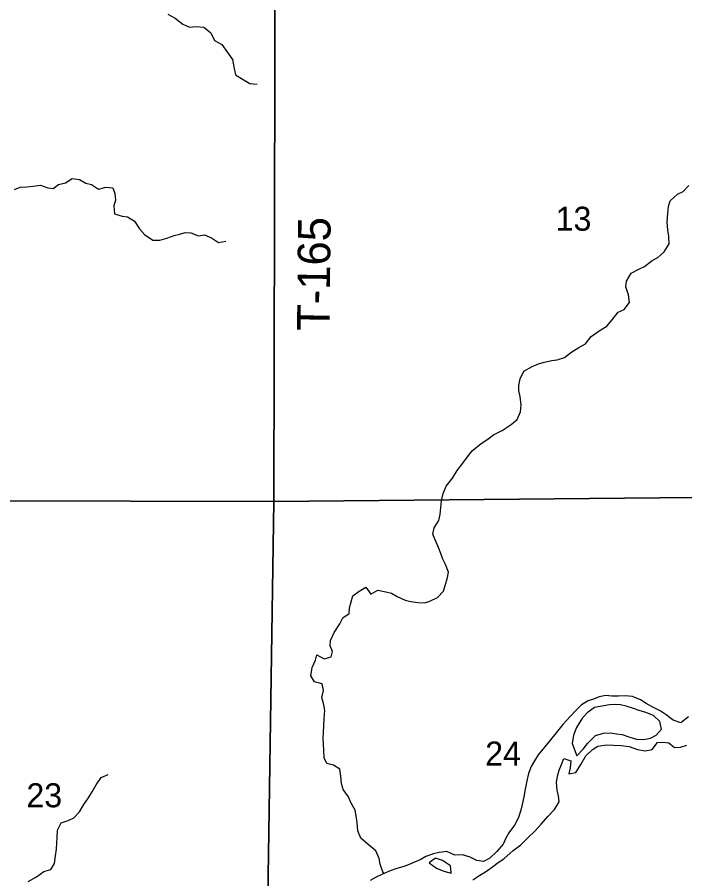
# Model space of a CAD drawing. Extents: x 1772825 to 1773716, y 1138558 to 1139032.
# Drawn here: x 1772830.255 to 1772830.837, y 1138559.298 to 1138560.049 of the extents above; entities that cross this region are included whole.
import ezdxf

# ---------------------------------------------------------------- set-up
doc = ezdxf.new("R2010")
doc.units = 0
for name, color, linetype in [('GM_X_Major_River', 7, 'Continuous'), ('GM_X_Minor_River', 7, 'Continuous'), ('GM_X_Section', 7, 'Continuous'), ('GM_X_Section_Text', 7, 'Continuous'), ('GM_X_Township_Road_Text', 7, 'Continuous')]:
    doc.layers.add(name, color=color, linetype=linetype)

msp = doc.modelspace()

# ---------------------------------------------------------------- linework, layer by layer
at = {"layer": 'GM_X_Major_River'}
for points in [[(1772830.84014, 1138559.43888), (1772830.83347, 1138559.43379), (1772830.82684, 1138559.43591), (1772830.8206, 1138559.44068), (1772830.81549, 1138559.44412), (1772830.80905, 1138559.44718), (1772830.80337, 1138559.45043), (1772830.79825, 1138559.45368), (1772830.79143, 1138559.45655), (1772830.78498, 1138559.45715), (1772830.7791, 1138559.45699), (1772830.77341, 1138559.45701), (1772830.76809, 1138559.45741), (1772830.76221, 1138559.4563), (1772830.75745, 1138559.45423), (1772830.7527, 1138559.45292), (1772830.74699, 1138559.44934), (1772830.74223, 1138559.44462), (1772830.73689, 1138559.43914), (1772830.7306, 1138559.43214), (1772830.72468, 1138559.42496), (1772830.71991, 1138559.41872), (1772830.71476, 1138559.41229), (1772830.70923, 1138559.40586), (1772830.70579, 1138559.40056), (1772830.70311, 1138559.39545), (1772830.70081, 1138559.38938), (1772830.69926, 1138559.38313), (1772830.69772, 1138559.37573), (1772830.69655, 1138559.3691), (1772830.69519, 1138559.36246), (1772830.69403, 1138559.35734), (1772830.69192, 1138559.35109), (1772830.68847, 1138559.34446), (1772830.68351, 1138559.33784), (1772830.68083, 1138559.33292), (1772830.67853, 1138559.3278), (1772830.67319, 1138559.32137), (1772830.6669, 1138559.31552), (1772830.66158, 1138559.31269), (1772830.6557, 1138559.31367), (1772830.64983, 1138559.31635), (1772830.64319, 1138559.31847), (1772830.63655, 1138559.31811), (1772830.62954, 1138559.32137), (1772830.62289, 1138559.32045), (1772830.61796, 1138559.31952), (1772830.61111, 1138559.31708), (1772830.60636, 1138559.31426), (1772830.60141, 1138559.312), (1772830.59666, 1138559.31012), (1772830.59191, 1138559.30844), (1772830.58507, 1138559.30638), (1772830.58012, 1138559.3045), (1772830.57347, 1138559.30168), (1772830.56738, 1138559.29867), (1772830.56263, 1138559.29604)], [(1772830.81573, 1138559.4321), (1772830.81507, 1138559.43482), (1772830.80978, 1138559.44015), (1772830.80295, 1138559.44265), (1772830.79727, 1138559.44438), (1772830.79234, 1138559.44611), (1772830.78571, 1138559.44823), (1772830.78078, 1138559.44939), (1772830.77603, 1138559.4496), (1772830.77129, 1138559.44924), (1772830.75837, 1138559.44702), (1772830.7519, 1138559.4423), (1772830.74713, 1138559.43701), (1772830.74254, 1138559.42963), (1772830.74005, 1138559.4228), (1772830.73888, 1138559.4156), (1772830.74282, 1138559.40495)], [(1772830.74282, 1138559.40495), (1772830.74835, 1138559.41062), (1772830.75216, 1138559.41554), (1772830.75903, 1138559.42253), (1772830.76606, 1138559.42459), (1772830.77232, 1138559.42494), (1772830.77744, 1138559.42416), (1772830.78237, 1138559.42338), (1772830.78901, 1138559.42127), (1772830.79488, 1138559.41953), (1772830.80134, 1138559.41913), (1772830.80703, 1138559.42024), (1772830.81198, 1138559.42288), (1772830.81675, 1138559.42798), (1772830.81573, 1138559.4321)], [(1772830.65202, 1138559.29679), (1772830.6583, 1138559.30075), (1772830.66306, 1138559.30377), (1772830.66915, 1138559.30811), (1772830.6741, 1138559.31188), (1772830.67924, 1138559.31508), (1772830.68743, 1138559.32226), (1772830.69409, 1138559.32736), (1772830.70019, 1138559.3334), (1772830.70629, 1138559.33907), (1772830.71182, 1138559.34512), (1772830.71754, 1138559.35193), (1772830.72345, 1138559.35816), (1772830.72728, 1138559.36479), (1772830.72673, 1138559.37011), (1772830.7258, 1138559.37504), (1772830.72507, 1138559.3815), (1772830.72604, 1138559.38719), (1772830.72739, 1138559.39231), (1772830.72931, 1138559.39742), (1772830.73142, 1138559.40254), (1772830.73749, 1138559.40061), (1772830.73708, 1138559.39435), (1772830.73573, 1138559.38923), (1772830.74181, 1138559.39035), (1772830.74639, 1138559.39716), (1772830.75079, 1138559.40473), (1772830.75651, 1138559.4104), (1772830.76127, 1138559.41342), (1772830.76886, 1138559.41433), (1772830.77493, 1138559.41431), (1772830.78157, 1138559.4139), (1772830.78859, 1138559.41311), (1772830.79579, 1138559.41042), (1772830.80243, 1138559.40925), (1772830.80851, 1138559.41037), (1772830.81309, 1138559.41661), (1772830.81784, 1138559.41678), (1772830.82296, 1138559.41619), (1772830.82788, 1138559.41218), (1772830.83319, 1138559.41254), (1772830.8387, 1138559.41403)], [(1772830.63282, 1138559.30637), (1772830.63253, 1138559.30902), (1772830.62571, 1138559.31342), (1772830.61965, 1138559.31553), (1772830.61394, 1138559.31157)], [(1772830.61394, 1138559.31157), (1772830.62056, 1138559.3068), (1772830.627, 1138559.3043), (1772830.63326, 1138559.30257), (1772830.63282, 1138559.30637)]]:
    msp.add_lwpolyline(points, dxfattribs=at)
at = {"layer": 'GM_X_Minor_River'}
for points in [[(1772830.3861, 1138560.05166), (1772830.39273, 1138560.04822), (1772830.39916, 1138560.04307), (1772830.40522, 1138560.04057), (1772830.41092, 1138560.04112), (1772830.41756, 1138560.04033), (1772830.4238, 1138560.03537), (1772830.427, 1138560.02872), (1772830.43325, 1138560.02528), (1772830.43815, 1138560.01823), (1772830.44268, 1138560.01214), (1772830.44379, 1138560.00588), (1772830.44509, 1138559.99885), (1772830.4519, 1138559.99484), (1772830.45758, 1138559.9914), (1772830.46403, 1138559.9908)], [(1772830.25259, 1138559.89891), (1772830.25734, 1138559.90098), (1772830.26323, 1138559.90115), (1772830.26892, 1138559.90188), (1772830.27519, 1138559.90261), (1772830.28144, 1138559.90031), (1772830.28619, 1138559.89972), (1772830.29095, 1138559.90331), (1772830.29703, 1138559.9048), (1772830.30293, 1138559.90857), (1772830.30918, 1138559.90759), (1772830.31467, 1138559.90434), (1772830.31961, 1138559.90318), (1772830.32585, 1138559.89917), (1772830.33231, 1138559.90085), (1772830.33819, 1138559.90026), (1772830.33988, 1138559.89551), (1772830.34061, 1138559.88962), (1772830.33907, 1138559.88469), (1772830.3398, 1138559.87767), (1772830.34625, 1138559.87555), (1772830.35118, 1138559.87515), (1772830.35724, 1138559.87114), (1772830.36157, 1138559.86467), (1772830.36592, 1138559.85972), (1772830.37311, 1138559.85476), (1772830.37918, 1138559.85473), (1772830.38526, 1138559.85641), (1772830.39173, 1138559.85885), (1772830.39667, 1138559.85997), (1772830.40142, 1138559.86128), (1772830.40616, 1138559.86107), (1772830.41298, 1138559.85857), (1772830.4183, 1138559.85931), (1772830.42436, 1138559.85663), (1772830.43042, 1138559.85262), (1772830.43669, 1138559.85373)], [(1772830.72568, 1138559.7504), (1772830.73195, 1138559.75227), (1772830.73843, 1138559.75718), (1772830.74452, 1138559.76095), (1772830.75042, 1138559.76434), (1772830.75519, 1138559.77058), (1772830.76242, 1138559.77548), (1772830.76889, 1138559.77963), (1772830.77366, 1138559.7853), (1772830.779, 1138559.79192), (1772830.78395, 1138559.79417), (1772830.78872, 1138559.80042), (1772830.78799, 1138559.80687), (1772830.78555, 1138559.8139), (1772830.78614, 1138559.81902), (1772830.79034, 1138559.82584), (1772830.79681, 1138559.82922), (1772830.80176, 1138559.83167), (1772830.80861, 1138559.83695), (1772830.81356, 1138559.83959), (1772830.81889, 1138559.8445), (1772830.82329, 1138559.8515), (1772830.82294, 1138559.85795), (1772830.8222, 1138559.86327), (1772830.82166, 1138559.87067), (1772830.82208, 1138559.87826), (1772830.82286, 1138559.88395), (1772830.82421, 1138559.88907), (1772830.83069, 1138559.89473), (1772830.83563, 1138559.89718), (1772830.8404, 1138559.90247)], [(1772830.57455, 1138559.30214), (1772830.57367, 1138559.30377), (1772830.57142, 1138559.31023), (1772830.57049, 1138559.31536), (1772830.56748, 1138559.32201), (1772830.56086, 1138559.32755), (1772830.55462, 1138559.33308), (1772830.55199, 1138559.33954), (1772830.55126, 1138559.34675), (1772830.55053, 1138559.35264), (1772830.5496, 1138559.35758), (1772830.54583, 1138559.36405), (1772830.54377, 1138559.36899), (1772830.53905, 1138559.37546), (1772830.53755, 1138559.38059), (1772830.53701, 1138559.38704), (1772830.53609, 1138559.39331), (1772830.53079, 1138559.39675), (1772830.52491, 1138559.3981), (1772830.52265, 1138559.40305), (1772830.52211, 1138559.40969), (1772830.52194, 1138559.41482), (1772830.52159, 1138559.41994), (1772830.5218, 1138559.42525), (1772830.5222, 1138559.43133), (1772830.52242, 1138559.4374), (1772830.52302, 1138559.44442), (1772830.52209, 1138559.44935), (1772830.52041, 1138559.45562), (1772830.52195, 1138559.46188), (1772830.52065, 1138559.46777), (1772830.5142, 1138559.46931), (1772830.511, 1138559.47464), (1772830.51198, 1138559.48204), (1772830.51485, 1138559.48829), (1772830.5162, 1138559.49303), (1772830.52245, 1138559.48939), (1772830.52872, 1138559.49126), (1772830.52969, 1138559.49601), (1772830.52781, 1138559.50076), (1772830.52802, 1138559.5055), (1772830.53127, 1138559.51251), (1772830.53605, 1138559.51989), (1772830.53892, 1138559.52519), (1772830.54444, 1138559.52915), (1772830.54465, 1138559.53408), (1772830.54619, 1138559.5392), (1772830.54754, 1138559.54451), (1772830.55306, 1138559.54847), (1772830.55896, 1138559.55186), (1772830.5633, 1138559.54596), (1772830.5692, 1138559.54935), (1772830.57641, 1138559.5478), (1772830.58115, 1138559.54683), (1772830.58607, 1138559.54378), (1772830.59327, 1138559.54071), (1772830.59801, 1138559.53936), (1772830.60427, 1138559.53857), (1772830.60996, 1138559.53836), (1772830.61471, 1138559.53967), (1772830.62136, 1138559.54287), (1772830.6267, 1138559.54835), (1772830.62805, 1138559.55346), (1772830.62998, 1138559.56029), (1772830.63095, 1138559.56503), (1772830.62832, 1138559.57168), (1772830.62606, 1138559.57644), (1772830.62438, 1138559.58138), (1772830.62212, 1138559.58651), (1772830.6193, 1138559.59316), (1772830.61723, 1138559.59829), (1772830.6184, 1138559.6036), (1772830.6226, 1138559.61004), (1772830.62376, 1138559.61535), (1772830.62435, 1138559.62142), (1772830.62495, 1138559.6273), (1772830.62631, 1138559.63374), (1772830.6288, 1138559.64018), (1772830.63433, 1138559.64699), (1772830.63835, 1138559.65381), (1772830.64254, 1138559.6591), (1772830.64751, 1138559.66553), (1772830.6517, 1138559.67083), (1772830.65951, 1138559.67744), (1772830.66446, 1138559.68064), (1772830.67017, 1138559.68479), (1772830.67759, 1138559.68874), (1772830.68559, 1138559.69383), (1772830.69073, 1138559.69837), (1772830.69379, 1138559.7048), (1772830.69439, 1138559.71087), (1772830.69328, 1138559.71828), (1772830.69235, 1138559.72322), (1772830.69237, 1138559.72796), (1772830.69335, 1138559.73384), (1772830.6966, 1138559.74028), (1772830.70383, 1138559.74442), (1772830.70934, 1138559.74667), (1772830.71448, 1138559.74817), (1772830.72094, 1138559.74966), (1772830.72568, 1138559.7504)], [(1772830.26428, 1138559.29522), (1772830.2717, 1138559.29936), (1772830.27798, 1138559.30389), (1772830.28406, 1138559.30576), (1772830.28731, 1138559.31087), (1772830.28828, 1138559.3177), (1772830.28907, 1138559.32339), (1772830.28947, 1138559.32889), (1772830.28968, 1138559.33363), (1772830.2899, 1138559.33989), (1772830.29315, 1138559.34652), (1772830.29942, 1138559.34839), (1772830.30418, 1138559.35065), (1772830.30932, 1138559.35613), (1772830.31295, 1138559.36238), (1772830.31697, 1138559.36824), (1772830.32021, 1138559.37354), (1772830.32384, 1138559.3796), (1772830.32805, 1138559.38604), (1772830.33432, 1138559.38848)]]:
    msp.add_lwpolyline(points, dxfattribs=at)
at = {"layer": 'GM_X_Section'}
for points in [[(1772830.47981, 1138560.12771), (1772831.00637, 1138560.13184), (1772830.99854, 1138559.63168), (1772830.4786, 1138559.62657)], [(1772829.98795, 1138560.12961), (1772830.47981, 1138560.12771), (1772830.4786, 1138559.62657), (1772829.97898, 1138559.62796)], [(1772829.97898, 1138559.62796), (1772830.4786, 1138559.62657), (1772830.47096, 1138559.12718), (1772829.98383, 1138559.12584)], [(1772830.4786, 1138559.62657), (1772830.99854, 1138559.63168), (1772830.99087, 1138559.12888), (1772830.47096, 1138559.12718)]]:
    msp.add_lwpolyline(points, close=True, dxfattribs=at)

# ---------------------------------------------------------------- texts
at = {"layer": 'GM_X_Section_Text'}
for s, p in [('13', (1772830.72437, 1138559.86291)), ('24', (1772830.66291, 1138559.3964)), ('23', (1772830.26291, 1138559.35999))]:
    msp.add_text(s, height=0.020928, rotation=0.00001, dxfattribs=at).set_placement(p)
at = {"layer": 'GM_X_Township_Road_Text'}
msp.add_text('T-165', height=0.028409, rotation=89.44064, dxfattribs=at).set_placement((1772830.52722, 1138559.77546))

doc.saveas('drawing.dxf')
